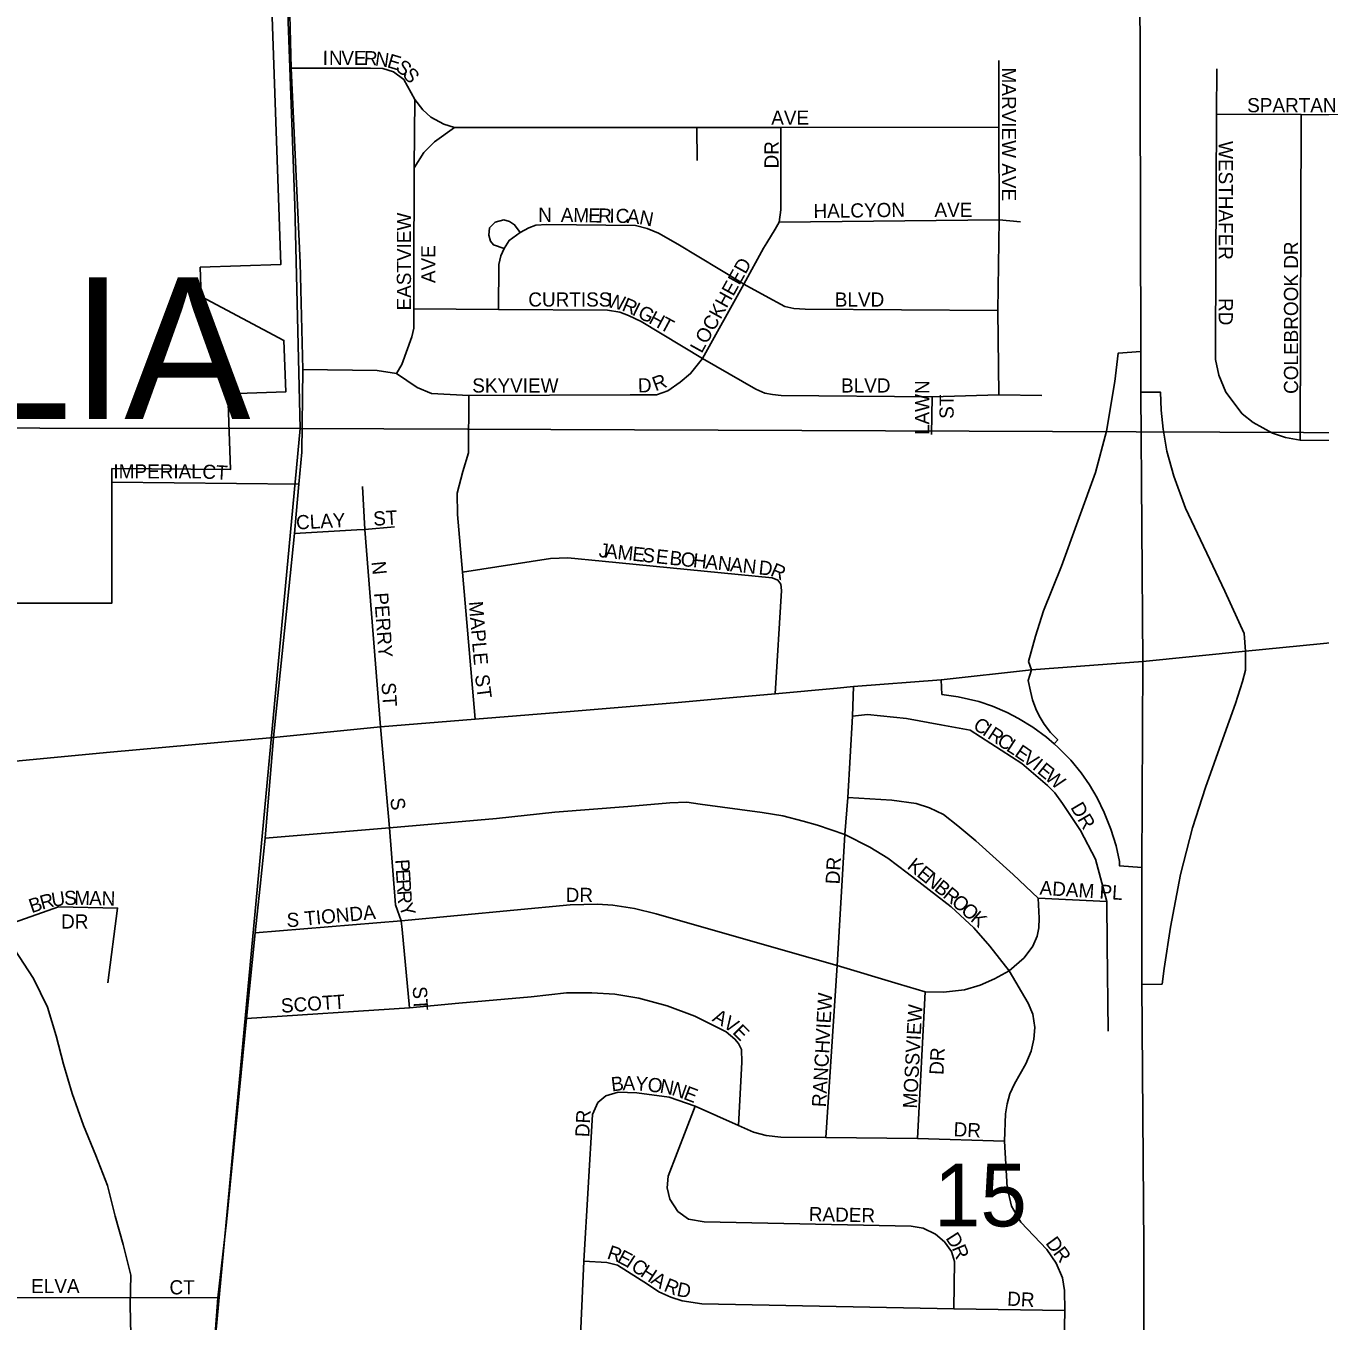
# Model space of a CAD drawing. Extents: x 8.5 to 81.5, y -1.2 to 22.4.
# Drawn here: x 52.1 to 52.966, y 19.27 to 20.137 of the extents above; entities that cross this region are included whole.
import ezdxf

# ---------------------------------------------------------------- set-up
doc = ezdxf.new("R2010")
doc.units = 0
for name, color, linetype in [('GM_X_City_Street', 7, 'Continuous'), ('GM_X_City_Street_Text', 7, 'Continuous'), ('GM_X_Corporation', 7, 'Continuous'), ('GM_X_Corporation_Text', 7, 'Continuous'), ('GM_X_Interchange_Ramps', 7, 'Continuous'), ('GM_X_Interstate_Route', 7, 'Continuous'), ('GM_X_Minor_River', 7, 'Continuous'), ('GM_X_Section', 7, 'Continuous'), ('GM_X_Section_Text', 7, 'Continuous'), ('GM_X_US_Route', 7, 'Continuous')]:
    doc.layers.add(name, color=color, linetype=linetype)

msp = doc.modelspace()

# ---------------------------------------------------------------- linework, layer by layer
at = {"layer": 'GM_X_City_Street'}
for points in [[(52.28009, 20.06027), (52.27792, 20.10848), (52.27666, 20.15295), (52.27021, 20.31076), (52.26776, 20.37063), (52.26394, 20.47178), (52.26008, 20.60622), (52.25396, 20.74399), (52.25341, 20.77262)], [(52.75125, 19.88987), (52.75046, 19.9464), (52.75132, 20.00701), (52.75116, 20.06891), (52.7511, 20.11355)], [(52.27792, 20.10848), (52.32792, 20.10843)], [(52.32792, 20.10843), (52.33089, 20.10843), (52.33922, 20.10817), (52.34624, 20.10609), (52.35312, 20.10076), (52.36053, 20.0875), (52.36587, 20.08061), (52.37119, 20.07567), (52.38003, 20.07099), (52.3872, 20.06868), (52.3981, 20.06865), (52.54928, 20.06865), (52.60544, 20.06865), (52.75116, 20.06891)], [(52.897, 20.10801), (52.89668, 20.07758), (52.89603, 19.92404), (52.89603, 19.9136), (52.89828, 19.903), (52.9031, 19.8916), (52.91402, 19.87715), (52.92133, 19.87128), (52.93426, 19.8643), (52.94293, 19.86133), (52.95272, 19.85947), (53.00227, 19.8594), (53.23711, 19.8591)], [(52.35992, 19.97021), (52.36006, 20.04183), (52.36053, 20.0875)], [(52.89668, 20.07758), (52.95337, 20.07749), (53.01038, 20.07702), (53.06755, 20.07708), (53.25743, 20.07718)], [(52.95272, 19.85947), (52.95337, 20.07749)], [(52.36006, 20.04183), (52.36667, 20.05211), (52.37366, 20.0591), (52.3872, 20.06868)], [(52.54941, 20.04668), (52.54928, 20.06865)], [(52.5959, 19.99151), (52.60164, 20.00076), (52.60422, 20.00537), (52.60537, 20.01361), (52.60544, 20.06865)], [(52.28121, 19.81007), (52.28304, 19.83013), (52.28498, 19.85151), (52.2857, 19.90691), (52.28378, 19.97827), (52.28009, 20.06027)], [(52.42028, 19.98774), (52.41311, 19.99019), (52.41113, 19.9927), (52.41012, 19.99669), (52.41061, 20.00169), (52.4143, 20.00539), (52.42004, 20.00699), (52.42392, 20.00579), (52.42726, 20.00365), (52.43102, 19.99851)], [(52.41653, 19.94699), (52.41674, 19.97712), (52.41809, 19.98285), (52.42028, 19.98774), (52.42372, 19.99316), (52.43102, 19.99851), (52.43683, 20.00169), (52.44141, 20.00336), (52.44891, 20.00388), (52.50826, 20.00315), (52.51596, 20.00128), (52.52356, 19.99805), (52.53637, 19.99076), (52.57857, 19.9653)], [(52.60422, 20.00537), (52.75132, 20.00701), (52.76567, 20.00555)], [(52.55297, 19.91427), (52.58072, 19.964), (52.59369, 19.98796), (52.5959, 19.99151)], [(52.34832, 19.90408), (52.35182, 19.91019), (52.35856, 19.92859), (52.35998, 19.93451), (52.35988, 19.94737), (52.35992, 19.97021)], [(52.57857, 19.9653), (52.58072, 19.964), (52.59478, 19.95609), (52.60808, 19.94903), (52.61415, 19.94765), (52.62165, 19.94724), (52.75046, 19.9464)], [(52.35988, 19.94737), (52.41653, 19.94699), (52.4895, 19.94659), (52.49762, 19.94524), (52.50358, 19.94294), (52.51184, 19.93901), (52.55297, 19.91427), (52.58861, 19.89379), (52.59465, 19.89107), (52.59979, 19.89016), (52.60553, 19.88956), (52.70651, 19.88865), (52.75125, 19.88987), (52.77997, 19.88956)], [(52.2857, 19.90691), (52.33547, 19.90612), (52.34832, 19.90408), (52.36211, 19.89484), (52.37167, 19.89077), (52.39659, 19.88951), (52.50454, 19.88983), (52.5221, 19.88998), (52.52977, 19.89265), (52.53792, 19.89829), (52.54497, 19.90408), (52.55297, 19.91427)], [(52.40081, 19.67283), (52.39251, 19.77133), (52.38905, 19.80986), (52.38889, 19.82403), (52.39267, 19.83868), (52.39646, 19.8512), (52.39659, 19.88951)], [(52.70606, 19.86326), (52.70651, 19.88865)], [(52.15792, 19.83156), (52.28304, 19.83013)], [(52.32935, 19.77179), (52.32714, 19.79986), (52.32551, 19.82861)], [(52.27623, 19.76022), (52.28002, 19.79708), (52.28121, 19.81007)], [(52.28002, 19.79708), (52.32182, 19.79955)], [(52.32182, 19.79955), (52.32714, 19.79986), (52.34686, 19.80151)], [(52.60146, 19.68993), (52.60576, 19.7589), (52.60543, 19.76318), (52.60346, 19.76582), (52.59951, 19.76746), (52.48588, 19.77866), (52.46282, 19.78096), (52.4513, 19.78031), (52.39251, 19.77133)], [(52.33754, 19.66771), (52.32935, 19.77179)], [(52.25709, 19.56122), (52.26044, 19.59327), (52.26596, 19.66055), (52.27623, 19.76022)], [(52.6354, 19.39308), (52.64306, 19.50805), (52.64823, 19.59577), (52.65027, 19.62047), (52.6534, 19.67485), (52.65403, 19.69477)], [(52.82368, 19.52212), (52.82342, 19.5509), (52.81589, 19.57926), (52.80586, 19.59854), (52.79366, 19.61653), (52.78866, 19.62354), (52.78366, 19.62852), (52.76654, 19.64335), (52.73206, 19.66545), (52.71248, 19.66921), (52.68944, 19.67328), (52.66343, 19.67594), (52.6534, 19.67485)], [(52.35202, 19.53214), (52.35146, 19.53795), (52.34758, 19.54874), (52.34369, 19.60014), (52.33754, 19.66771)], [(52.25381, 19.52994), (52.35146, 19.53795), (52.46451, 19.54871), (52.48271, 19.54922), (52.49308, 19.54839), (52.50759, 19.54623), (52.52191, 19.54273), (52.60857, 19.51785), (52.64306, 19.50805), (52.6838, 19.4958), (52.70198, 19.49049), (52.7142, 19.49036), (52.7282, 19.49176), (52.73864, 19.49494), (52.74818, 19.49927), (52.75812, 19.50464), (52.76803, 19.51327), (52.77401, 19.52116), (52.77681, 19.52765), (52.77796, 19.53338), (52.77821, 19.53987), (52.77758, 19.55323), (52.76078, 19.56901), (52.73572, 19.59161), (52.72374, 19.60159), (52.7142, 19.60922), (52.70476, 19.61358), (52.69578, 19.61658), (52.67959, 19.61864), (52.65027, 19.62047)], [(52.75506, 19.3906), (52.75573, 19.4089), (52.75668, 19.41546), (52.75863, 19.42233), (52.76171, 19.42885), (52.76923, 19.44227), (52.77269, 19.45081), (52.77449, 19.45891), (52.77534, 19.46655), (52.7739, 19.47562), (52.77076, 19.48301), (52.75812, 19.50464), (52.74522, 19.5211), (52.73452, 19.53324), (52.71934, 19.54732), (52.6899, 19.57015), (52.67683, 19.57982), (52.66495, 19.58728), (52.64823, 19.59577), (52.62999, 19.60205), (52.6204, 19.60476), (52.60674, 19.60824), (52.59291, 19.61037), (52.55149, 19.6161), (52.54256, 19.61733), (52.53111, 19.61692), (52.50296, 19.61456), (52.45431, 19.61064), (52.41517, 19.60642), (52.34369, 19.60014), (52.26044, 19.59327)], [(52.22027, 19.09419), (52.22045, 19.12548), (52.22221, 19.19595), (52.22886, 19.28586), (52.23454, 19.33637), (52.24802, 19.47263), (52.25381, 19.52994), (52.25709, 19.56122)], [(52.77758, 19.55323), (52.82342, 19.5509)], [(52.15521, 19.49645), (52.16173, 19.54655), (52.1223, 19.54744), (52.09263, 19.53695)], [(52.35704, 19.4798), (52.35202, 19.53214)], [(52.8242, 19.46425), (52.82368, 19.52212)], [(52.24802, 19.47263), (52.35704, 19.4798), (52.38988, 19.48298), (52.43836, 19.48706), (52.46208, 19.48989), (52.47905, 19.48988), (52.49423, 19.48896), (52.51039, 19.48629), (52.52935, 19.48107), (52.54793, 19.4742), (52.56881, 19.46364), (52.57466, 19.45893), (52.57714, 19.45588), (52.57911, 19.45193), (52.57937, 19.44341), (52.57708, 19.40116)], [(52.6967, 19.3924), (52.70198, 19.49049)], [(52.47941, 19.4085), (52.48296, 19.41641), (52.48841, 19.42091), (52.4966, 19.42336), (52.50914, 19.42295), (52.53056, 19.42009), (52.54816, 19.41395), (52.57708, 19.40116), (52.58703, 19.39663), (52.59544, 19.39443), (52.60545, 19.39335), (52.6354, 19.39308), (52.6967, 19.3924), (52.75506, 19.3906)], [(52.72118, 19.27846), (52.72146, 19.31003), (52.71952, 19.31672), (52.71476, 19.32327), (52.70882, 19.32847), (52.70049, 19.33249), (52.69246, 19.33368), (52.554, 19.33665), (52.54359, 19.33844), (52.53645, 19.34364), (52.53109, 19.35182), (52.52931, 19.35941), (52.53006, 19.36714), (52.54816, 19.41395)], [(52.46514, 19.1207), (52.47351, 19.31025), (52.47941, 19.4085)], [(52.6891, 18.85966), (52.71102, 18.86466), (52.73244, 18.86466), (52.74812, 18.86534), (52.76272, 18.87066), (52.77527, 18.88075), (52.78182, 18.88893), (52.78577, 18.89848), (52.78904, 18.9113), (52.78986, 18.9244), (52.79054, 18.98674), (52.79191, 19.04921), (52.79268, 19.11362), (52.79368, 19.16829), (52.79423, 19.22285), (52.79532, 19.27741), (52.79505, 19.29078), (52.79382, 19.29924), (52.78959, 19.30892), (52.78331, 19.31806), (52.76585, 19.33634), (52.75971, 19.34711), (52.75671, 19.35966), (52.75506, 19.3906)], [(52.47351, 19.31025), (52.489, 19.30941), (52.49607, 19.30773), (52.51626, 19.29494), (52.52366, 19.2899), (52.53173, 19.28619), (52.53947, 19.28384), (52.55259, 19.28182), (52.72118, 19.27846), (52.79532, 19.27741)], [(52.08257, 19.28608), (52.22886, 19.28586)]]:
    msp.add_lwpolyline(points, dxfattribs=at)
at = {"layer": 'GM_X_Corporation'}
for points in [[(52.25936, 21.01123), (52.2567, 20.86959), (52.25158, 20.86932), (52.23976, 20.8687), (52.27094, 19.9771), (52.217, 19.97523), (52.21768, 19.95576), (52.27298, 19.92635), (52.27419, 19.89183), (52.23539, 19.89048), (52.23716, 19.83987), (52.15793, 19.84059), (52.15789, 19.7505), (52.03952, 19.75051), (52.03953, 19.65129), (51.91664, 19.6402), (51.55407, 19.60748), (51.42733, 19.59604), (51.3727, 19.59111), (49.93264, 19.46099)], [(52.03952, 19.75051), (52.15789, 19.7505), (52.15793, 19.84059), (52.23716, 19.83987), (52.23539, 19.89048), (52.27419, 19.89183), (52.27298, 19.92635), (52.21768, 19.95576), (52.217, 19.97523), (52.27094, 19.9771), (52.23976, 20.8687), (52.14198, 20.86359), (52.14408, 20.98399)]]:
    msp.add_lwpolyline(points, dxfattribs=at)
at = {"layer": 'GM_X_Interchange_Ramps'}
for points in [[(52.84625, 19.91895), (52.83109, 19.91787), (52.82883, 19.89888), (52.82324, 19.86558), (52.8158, 19.83802), (52.7931, 19.7753), (52.78114, 19.7453), (52.77577, 19.72834), (52.77105, 19.71145), (52.77295, 19.706)], [(52.91623, 19.71837), (52.91524, 19.73021), (52.90241, 19.75858), (52.87612, 19.8141), (52.86816, 19.83554), (52.86354, 19.85216), (52.86105, 19.86697), (52.85978, 19.87966), (52.85921, 19.89169), (52.84625, 19.89169)], [(52.84691, 19.49545), (52.86036, 19.49574), (52.86184, 19.50613), (52.86594, 19.53368), (52.87274, 19.5691), (52.88076, 19.60029), (52.88941, 19.62725), (52.90105, 19.65967), (52.90942, 19.6833), (52.91419, 19.69814), (52.91619, 19.7057), (52.91623, 19.71837)], [(52.77295, 19.706), (52.77077, 19.69868), (52.77224, 19.69154), (52.77373, 19.68593), (52.77599, 19.67985), (52.77822, 19.67518), (52.78149, 19.66968), (52.78576, 19.66396), (52.79062, 19.65915), (52.7882, 19.65636)], [(52.71252, 19.69924), (52.71311, 19.68942), (52.72392, 19.68787), (52.73779, 19.6847), (52.74693, 19.68158), (52.75664, 19.67742), (52.76432, 19.67346), (52.77394, 19.66755), (52.78301, 19.66088), (52.7882, 19.65636), (52.79092, 19.65399), (52.79926, 19.64541), (52.80619, 19.63694), (52.81179, 19.6289), (52.81684, 19.62037), (52.82169, 19.61049), (52.826, 19.59943), (52.82968, 19.58825), (52.83185, 19.57767), (52.83197, 19.57469), (52.84691, 19.5737)]]:
    msp.add_lwpolyline(points, dxfattribs=at)
at = {"layer": 'GM_X_Interstate_Route'}
msp.add_lwpolyline([(52.78977, 18.30758), (52.79029, 18.31393), (52.83441, 18.83323), (52.83901, 18.91871), (52.84494, 19.05878), (52.84691, 19.14757), (52.84822, 19.23239), (52.84822, 19.31986), (52.84691, 19.49545), (52.84691, 19.5737), (52.84756, 19.71157), (52.84625, 19.89169), (52.84625, 19.91895), (52.84559, 20.18068), (52.84625, 20.26222), (52.84688, 20.36441), (52.84559, 20.48516), (52.84602, 20.52332), (52.84594, 20.85146)], dxfattribs=at)
at = {"layer": 'GM_X_Minor_River'}
msp.add_lwpolyline([(52.1705, 19.26134), (52.17012, 19.28071), (52.1705, 19.30085), (52.16555, 19.32136), (52.16022, 19.34035), (52.1549, 19.36087), (52.14729, 19.381), (52.13892, 19.40113), (52.13131, 19.42241), (52.12561, 19.44216), (52.12066, 19.46115), (52.11496, 19.48015), (52.10545, 19.49952), (52.09252, 19.51928)], dxfattribs=at)
at = {"layer": 'GM_X_Section'}
for points in [[(52.24935, 20.87158), (52.28033, 20.01658), (52.28397, 19.8673), (51.23908, 19.86864), (51.28541, 20.86876)], [(52.24935, 20.87158), (53.29223, 20.86382), (53.26973, 19.86289), (53.23452, 19.86355), (52.28397, 19.8673), (52.28033, 20.01658)], [(52.28397, 19.8673), (52.22193, 19.20227), (52.2136, 18.89831), (51.6895, 18.86113), (51.22018, 18.85778), (51.2184, 19.37023), (51.23908, 19.86864)], [(52.28397, 19.8673), (53.23452, 19.86355), (53.22945, 18.86267), (52.2136, 18.89831), (52.22193, 19.20227)]]:
    msp.add_lwpolyline(points, close=True, dxfattribs=at)
at = {"layer": 'GM_X_US_Route'}
for points in [[(52.64301, 19.69376), (52.65403, 19.69477), (52.71252, 19.69924), (52.77295, 19.706), (52.84756, 19.71157), (52.91623, 19.71837), (53.02955, 19.72947), (53.04249, 19.73056)], [(52.4644, 19.67804), (52.5367, 19.68397), (52.57357, 19.68737)], [(52.57357, 19.68737), (52.60146, 19.68993), (52.64301, 19.69376)], [(52.05585, 19.64124), (52.15679, 19.65085), (52.26596, 19.66055), (52.33754, 19.66771), (52.40081, 19.67283), (52.4644, 19.67804)]]:
    msp.add_lwpolyline(points, dxfattribs=at)

# ---------------------------------------------------------------- texts
at = {"layer": 'GM_X_City_Street_Text'}
for s, height, rotation, p in [('I', 0.00947, 359.86889, (52.29895, 20.11061)), ('N', 0.00947, 359.86884, (52.30312, 20.1106)), ('V', 0.00947, 359.86884, (52.31145, 20.11058)), ('E', 0.00947, 359.86339, (52.31978, 20.11056)), ('R', 0.00947, 357.8142, (52.32636, 20.11055)), ('N', 0.00947, 352.15117, (52.3336, 20.11028)), ('E', 0.00947, 343.20656, (52.34148, 20.10923)), ('S', 0.00947, 320.63177, (52.347, 20.10776)), ('S', 0.00947, 310.26043, (52.35183, 20.10385)), ('MARVIEW AVE', 0.0094697, 270, (52.75323, 20.10883)), ('SPARTAN', 0.00947, 0.00001, (52.91728, 20.07895)), ('AVE', 0.00947, 0.00001, (52.59895, 20.07061)), ('WESTHAFER', 0.00947, 270, (52.89823, 20.05966)), ('DR', 0.00947, 90, (52.60384, 20.04133)), ('HALCYON', 0.00947, 0.84526, (52.62726, 20.00811)), ('AVE', 0.00947, 0.00001, (52.70812, 20.00895)), ('EASTVIEW', 0.00947, 90, (52.358, 19.94633)), ('N', 0.00947, 0.00001, (52.44312, 20.00561)), ('A', 0.00947, 358.99453, (52.45814, 20.00561)), ('M', 0.00947, 358.9799, (52.46648, 20.00547)), ('E', 0.00947, 358.98916, (52.47647, 20.00529)), ('R', 0.00947, 359.00801, (52.48314, 20.00517)), ('I', 0.00947, 358.99491, (52.49064, 20.00504)), ('C', 0.00947, 358.98001, (52.49481, 20.00497)), ('A', 0.00947, 355.64655, (52.50216, 20.00484)), ('N', 0.00947, 348.7801, (52.51018, 20.00425)), ('COLEBROOK DR', 0.0094697, 90, (52.95134, 19.8905)), ('AVE', 0.00947, 90, (52.3743, 19.96466)), ('LOCKHEED', 0.00947, 61.02024, (52.55239, 19.91719)), ('CURTISS', 0.00947, 0.00001, (52.43645, 19.94895)), ('W', 0.00947, 346.63242, (52.4883, 19.94895)), ('BLVD', 0.00947, 0.00001, (52.64145, 19.94894)), ('R', 0.00947, 337.2064, (52.49846, 19.94657)), ('I', 0.00947, 334.2171, (52.50525, 19.94372)), ('G', 0.00947, 333.21989, (52.50896, 19.94193)), ('RD', 0.00947, 270, (52.89823, 19.95466)), ('H', 0.00947, 331.61634, (52.51634, 19.9382)), ('T', 0.00947, 331.55307, (52.52367, 19.93425)), ('R', 0.00947, 20.3438, (52.52149, 19.89225)), ('SKYVIEW', 0.00947, 0.00001, (52.39895, 19.89144)), ('D', 0.00947, 1.22399, (52.50984, 19.89144)), ('BLVD', 0.00947, 0.00001, (52.64562, 19.89144)), ('LAWN', 0.00947, 90, (52.70467, 19.863)), ('ST', 0.00947, 90, (52.72096, 19.87383)), ('IMPERIAL', 0.00947, 0.00001, (52.15895, 19.83394)), ('CT', 0.00947, 356.82151, (52.21822, 19.83394)), ('CLAY', 0.00947, 3.01701, (52.28136, 19.79977)), ('ST', 0.00947, 3.57378, (52.33301, 19.80227)), ('J', 0.00947, 353.82395, (52.48331, 19.78143)), ('A', 0.00947, 353.80222, (52.48745, 19.78099)), ('M', 0.00947, 353.82118, (52.49573, 19.78009)), ('E', 0.00947, 353.82939, (52.50568, 19.779)), ('S', 0.00947, 353.81367, (52.5123, 19.77829)), ('E', 0.00947, 353.82939, (52.52142, 19.7773)), ('B', 0.00947, 353.83611, (52.53054, 19.77631)), ('O', 0.00947, 353.80222, (52.53799, 19.7755)), ('H', 0.00947, 353.8299, (52.54628, 19.7746)), ('A', 0.00947, 353.80222, (52.55457, 19.77371)), ('N', 0.00947, 353.81954, (52.56285, 19.77281)), ('N', 0.00947, 275.70844, (52.33156, 19.77817)), ('A', 0.00947, 353.8299, (52.57114, 19.77191)), ('N', 0.00947, 353.80222, (52.57942, 19.77101)), ('D', 0.00947, 353.82395, (52.5902, 19.76984)), ('R', 0.00947, 336.72806, (52.59777, 19.76914)), ('PERRY', 0.00947, 274.1613, (52.33323, 19.75729)), ('MAPLE', 0.00947, 274.86678, (52.39656, 19.75148)), ('ST', 0.00947, 273.57465, (52.33823, 19.69727)), ('ST', 0.00947, 277.12166, (52.40072, 19.70238)), ('C', 0.00947, 326.59951, (52.73326, 19.66699)), ('I', 0.00947, 326.57665, (52.73952, 19.66286)), ('R', 0.00947, 326.59633, (52.743, 19.66056)), ('C', 0.00947, 326.59951, (52.74926, 19.65643)), ('L', 0.00947, 326.59024, (52.75553, 19.6523)), ('E', 0.00947, 325.94611, (52.76107, 19.64865)), ('V', 0.00947, 322.40876, (52.76646, 19.64501)), ('I', 0.00947, 320.9443, (52.77302, 19.63996)), ('E', 0.00947, 320.74712, (52.77625, 19.63734)), ('W', 0.00947, 319.1051, (52.78135, 19.63317)), ('S', 0.00947, 277.1183, (52.34405, 19.61989)), ('DR', 0.00947, 300.46387, (52.79882, 19.6139)), ('P', 0.00947, 273.74503, (52.3474, 19.57891)), ('DR', 0.00947, 86.98841, (52.64468, 19.56226)), ('K', 0.00947, 320.9443, (52.68924, 19.57355)), ('E', 0.00947, 320.94665, (52.69571, 19.5683)), ('E', 0.00947, 273.74503, (52.34783, 19.57225)), ('N', 0.00947, 320.93053, (52.70089, 19.5641)), ('B', 0.00947, 320.97093, (52.70736, 19.55884)), ('U', 0.00947, 8.60838, (52.1182, 19.54727)), ('S', 0.00947, 2.05734, (52.12615, 19.54849)), ('M', 0.00947, 358.78182, (52.13267, 19.54873)), ('A', 0.00947, 358.78182, (52.14267, 19.54851)), ('N', 0.00947, 358.78182, (52.151, 19.54834)), ('R', 0.00947, 273.75379, (52.34827, 19.5656)), ('R', 0.00947, 273.743, (52.34876, 19.55811)), ('DR', 0.00947, 0.00001, (52.46145, 19.55061)), ('R', 0.00947, 320.7106, (52.71318, 19.55412)), ('ADAM PL', 0.00947, 356.31065, (52.77822, 19.55549)), ('B', 0.00947, 18.43495, (52.10426, 19.54304)), ('R', 0.00947, 15.15942, (52.11124, 19.54537)), ('TIONDA', 0.00947, 5.38661, (52.28712, 19.53477)), ('Y', 0.00947, 288.77158, (52.34977, 19.54802)), ('O', 0.00947, 318.9436, (52.71893, 19.54942)), ('O', 0.00947, 318.41728, (52.7252, 19.54397)), ('DR', 0.00947, 0.00001, (52.12395, 19.53283)), ('S', 0.00947, 0.00001, (52.27478, 19.53395)), ('K', 0.00947, 319.70911, (52.73161, 19.53828)), ('SCOTT', 0.00947, 3.89847, (52.27133, 19.47644)), ('ST', 0.00947, 273.57465, (52.35906, 19.49394)), ('VIEW', 0.00947, 86.81579, (52.63801, 19.45726)), ('MOSSVIEW', 0.00947, 86.90752, (52.69634, 19.41226)), ('A', 0.00947, 330.97087, (52.55893, 19.47125)), ('V', 0.00947, 326.46756, (52.56605, 19.46731)), ('E', 0.00947, 315, (52.57261, 19.46302)), ('RANCH', 0.00947, 86.49837, (52.6355, 19.41311)), ('DR', 0.00947, 86.98901, (52.7141, 19.43475)), ('B', 0.00947, 6.76658, (52.49237, 19.42383)), ('A', 0.00947, 359.69396, (52.49951, 19.4247)), ('Y', 0.00947, 355.16375, (52.50764, 19.42467)), ('O', 0.00947, 353.31953, (52.51587, 19.42397)), ('N', 0.00947, 350.02747, (52.524, 19.42302)), ('N', 0.00947, 340.87394, (52.53182, 19.42168)), ('E', 0.00947, 339.13703, (52.53963, 19.41897)), ('DR', 0.00947, 86.98901, (52.47721, 19.39309)), ('DR', 0.00947, 356.98902, (52.72071, 19.39394)), ('RADER', 0.00947, 358.77707, (52.62399, 19.33716)), ('D', 0.00947, 302.56844, (52.71525, 19.32571)), ('D', 0.00947, 306.32787, (52.78205, 19.32238)), ('R', 0.00947, 341.56505, (52.48856, 19.31223)), ('E', 0.00947, 332.44509, (52.4953, 19.31001)), ('I', 0.00947, 326.98896, (52.50101, 19.30705)), ('R', 0.00947, 292.47789, (52.71954, 19.31908)), ('R', 0.00947, 307.12682, (52.78708, 19.31555)), ('C', 0.00947, 326.56587, (52.50449, 19.30479)), ('H', 0.00947, 326.56561, (52.51075, 19.30065)), ('ELVA', 0.00947, 0.00001, (52.10395, 19.28895)), ('CT', 0.00947, 0.00001, (52.19645, 19.28811)), ('A', 0.00947, 327.18732, (52.5178, 19.296)), ('R', 0.00947, 337.78529, (52.52649, 19.2906)), ('D', 0.00947, 348.08573, (52.53521, 19.28722)), ('DR', 0.00947, 356.98842, (52.75655, 19.28061))]:
    msp.add_text(s, height=height, rotation=rotation, dxfattribs=at).set_placement(p)
at = {"layer": 'GM_X_Corporation_Text'}
msp.add_text('VANDALIA', height=0.094697, rotation=0.00001, dxfattribs=at).set_placement((51.62432, 19.87373))
at = {"layer": 'GM_X_Section_Text'}
msp.add_text('15', height=0.041856, rotation=0.00001, dxfattribs=at).set_placement((52.7077, 19.33358))

doc.saveas('drawing.dxf')
